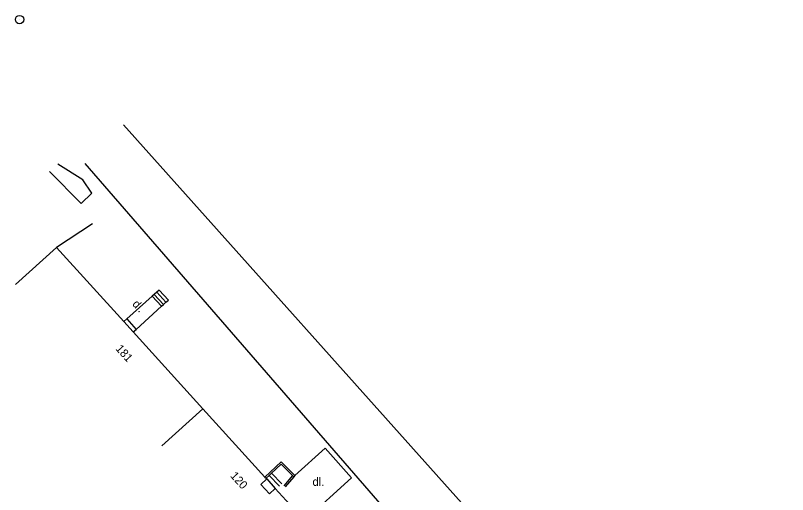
# Model space of a CAD drawing. Extents: x -582162 to -561283, y -1187583 to -1183539.
# Drawn here: x -570232.7 to -570163.1, y -1185212.7 to -1185169.5 of the extents above; entities that cross this region are included whole.
import ezdxf

# ---------------------------------------------------------------- set-up
doc = ezdxf.new("R2010")
doc.units = 0
for name, color, linetype in [('Vrstva 1', 7, 'Continuous'), ('Vrstva 10', 7, 'Continuous'), ('Vrstva 14', 7, 'Continuous'), ('Vrstva 4', 7, 'Continuous'), ('Vrstva 6', 7, 'Continuous'), ('Vrstva 9', 7, 'Continuous')]:
    doc.layers.add(name, color=color, linetype=linetype)

# ---------------------------------------------------------------- blocks, each defined once
blk = doc.blocks.new('1.079')
at = {"layer": 'Vrstva 1'}
for radius in [0.75, 0.001]:
    blk.add_circle((0, -0.001), radius, dxfattribs=at)

msp = doc.modelspace()

# ---------------------------------------------------------------- linework, layer by layer
at = {"layer": 'Vrstva 10'}
for points in [[(-570222.99, -1185179.35), (-570190.7, -1185215.47), (-570163.06, -1185246.46)], [(-570229.66, -1185183.55), (-570226.78, -1185186.44), (-570225.84, -1185185.51), (-570226.65, -1185184.3), (-570228.89, -1185182.9)], [(-570226.45, -1185182.85), (-570195.12, -1185218.99)], [(-570225.78, -1185188.3), (-570229.01, -1185190.41)], [(-570219.98, -1185194.47), (-570220.2, -1185194.67)], [(-570219.15, -1185195.37), (-570218.92, -1185195.17), (-570219.75, -1185194.27), (-570219.98, -1185194.47)], [(-570219.98, -1185194.47), (-570219.15, -1185195.37)], [(-570222.67, -1185196.86), (-570220.39, -1185194.83)], [(-570220.2, -1185194.67), (-570220.39, -1185194.83)], [(-570220.39, -1185194.83), (-570219.56, -1185195.73)], [(-570220.2, -1185194.67), (-570219.37, -1185195.57)], [(-570219.56, -1185195.73), (-570221.83, -1185197.83)], [(-570219.56, -1185195.73), (-570219.37, -1185195.57)], [(-570219.37, -1185195.57), (-570219.15, -1185195.37)], [(-570222.67, -1185196.86), (-570222.96, -1185197.11)], [(-570222.67, -1185196.86), (-570221.83, -1185197.83)], [(-570222.11, -1185198.05), (-570221.83, -1185197.83)], [(-570207.51, -1185211), (-570204.78, -1185208.55)], [(-570204.78, -1185208.55), (-570202.39, -1185211.22), (-570206.65, -1185215.08)], [(-570209.83, -1185211), (-570208.89, -1185211.99)], [(-570209.61, -1185210.8), (-570208.68, -1185211.77)]]:
    msp.add_lwpolyline(points, dxfattribs=at)
at = {"layer": 'Vrstva 4'}
for points in [[(-570232.72, -1185193.76), (-570229.01, -1185190.41)], [(-570229.01, -1185190.41), (-570222.96, -1185197.11)], [(-570222.96, -1185197.11), (-570222.11, -1185198.05)], [(-570222.11, -1185198.05), (-570215.82, -1185205)], [(-570219.53, -1185208.35), (-570215.82, -1185205)], [(-570215.82, -1185205), (-570210.21, -1185211.16)], [(-570209.28, -1185212.19), (-570209.81, -1185212.68), (-570210.59, -1185211.83), (-570210.05, -1185211.33)], [(-570210.21, -1185211.16), (-570210.11, -1185211.27)], [(-570210.11, -1185211.27), (-570210.05, -1185211.33)], [(-570210.05, -1185211.33), (-570209.28, -1185212.19)], [(-570209.28, -1185212.19), (-570206.65, -1185215.08), (-570205.99, -1185215.8)]]:
    msp.add_lwpolyline(points, dxfattribs=at)
at = {"layer": 'Vrstva 9'}
for points in [[(-570210.21, -1185211.16), (-570208.75, -1185209.79), (-570207.51, -1185211), (-570207.61, -1185211.12)], [(-570209.61, -1185210.8), (-570208.75, -1185210), (-570207.72, -1185211.01)], [(-570210.11, -1185211.27), (-570209.83, -1185211)], [(-570209.83, -1185211), (-570209.61, -1185210.8)], [(-570207.72, -1185211.01), (-570208.5, -1185211.94)], [(-570207.61, -1185211.12), (-570208.39, -1185212.04)], [(-570207.72, -1185211.01), (-570207.61, -1185211.12)]]:
    msp.add_lwpolyline(points, dxfattribs=at)

# ---------------------------------------------------------------- block references
at = {"layer": 'Vrstva 1', "xscale": 0.5, "yscale": 0.5}
msp.add_blockref('1.079', (-570232.35, -1185169.84), dxfattribs=at)

# ---------------------------------------------------------------- texts
at = {"layer": 'Vrstva 14'}
msp.add_text(' dl.', height=0.75, rotation=312.683, dxfattribs=at).set_placement((-570222.42, -1185195.37))
msp.add_text('dl.', height=0.75, dxfattribs=at).set_placement((-570205.92, -1185211.95))
at = {"layer": 'Vrstva 6'}
for s, rotation, p in [('181', 312.115, (-570223.74, -1185199.6)), ('120', 312.325, (-570213.39, -1185211.08))]:
    msp.add_text(s, height=0.75, rotation=rotation, dxfattribs=at).set_placement(p)

doc.saveas('drawing.dxf')
